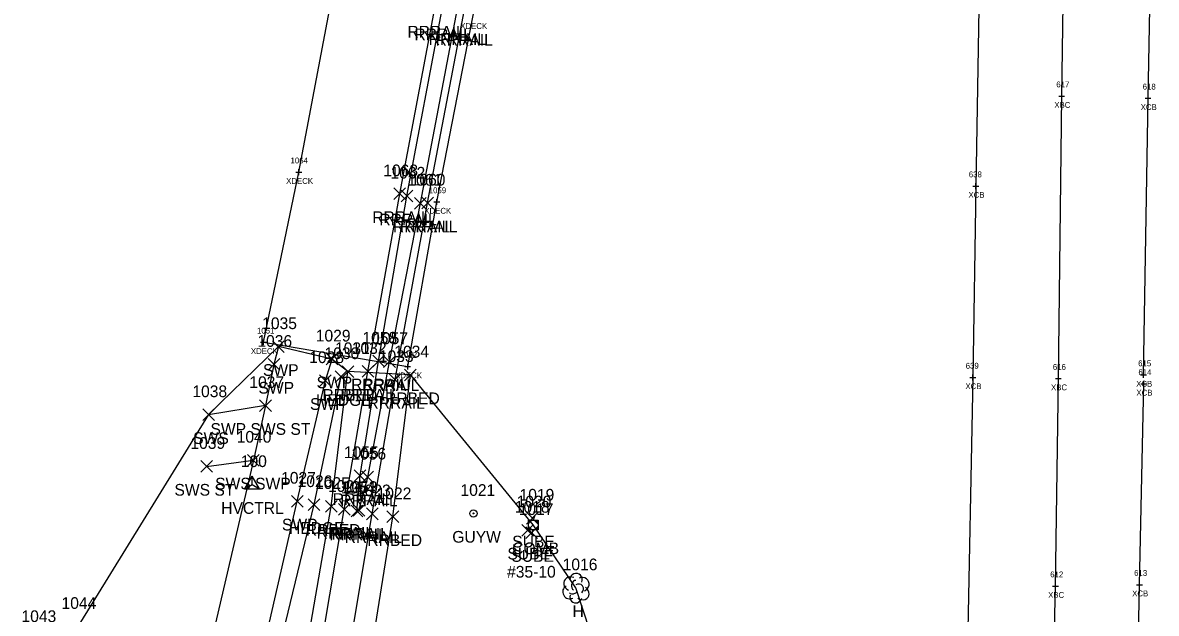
# Model space of a CAD drawing. Extents: x 1715662 to 1717487, y 887396 to 890004.
# Drawn here: x 1716437.2 to 1716631.1, y 888399.3 to 888500.3 of the extents above; entities that cross this region are included whole.
import ezdxf

# ---------------------------------------------------------------- set-up
doc = ezdxf.new("R2010")
doc.units = 0
for name, color, linetype in [('B_A', 7, 'Continuous'), ('B_I', 7, 'Continuous'), ('B_TIC', 7, 'Continuous'), ('BDC', 7, 'Continuous'), ('BELB', 7, 'Continuous'), ('C_A', 7, 'Continuous'), ('C_I', 7, 'Continuous'), ('CPSM', 7, 'Continuous'), ('L_A', 7, 'Continuous'), ('L_I', 7, 'Continuous'), ('L_TIC', 7, 'Continuous'), ('LAHR', 7, 'Continuous'), ('LSOGP', 7, 'Continuous'), ('LTD', 7, 'Continuous'), ('R_A', 7, 'Continuous'), ('R_I', 7, 'Continuous'), ('R_TIC', 7, 'Continuous'), ('RR', 7, 'Continuous'), ('RRB', 7, 'Continuous'), ('RSW', 7, 'Continuous'), ('U_A', 7, 'Continuous'), ('U_C', 7, 'Continuous'), ('U_I', 7, 'Continuous'), ('U_TIC', 7, 'Continuous'), ('UP', 7, 'Continuous'), ('UPGW', 7, 'Continuous')]:
    doc.layers.add(name, color=color, linetype=linetype)

msp = doc.modelspace()

# ---------------------------------------------------------------- linework, layer by layer
at = {"layer": 'B_TIC'}
for p, q in [((1716614.94, 888487.77), (1716615.02, 888487.77)), ((1716629.71, 888487.4), (1716629.79, 888487.4)), ((1716484.45, 888474.77), (1716484.52, 888474.77)), ((1716600.26, 888472.39), (1716600.34, 888472.39)), ((1716508.08, 888469.67), (1716508.15, 888469.67)), ((1716478.41, 888445.68), (1716478.49, 888445.68)), ((1716478.41, 888445.68), (1716478.49, 888445.68)), ((1716503.09, 888441.52), (1716503.16, 888441.52)), ((1716599.73, 888439.67), (1716599.81, 888439.67)), ((1716614.38, 888439.47), (1716614.45, 888439.47)), ((1716628.95, 888440.09), (1716629.02, 888440.09)), ((1716628.99, 888438.57), (1716629.06, 888438.57)), ((1716628.25, 888404.24), (1716628.33, 888404.24)), ((1716613.89, 888403.99), (1716613.97, 888403.99))]:
    msp.add_line(p, q, dxfattribs=at)
for points in [[(1716614.44, 888487.77), (1716615.44, 888487.77)], [(1716614.94, 888487.27), (1716614.94, 888488.27)], [(1716629.71, 888486.9), (1716629.71, 888487.9)], [(1716629.21, 888487.4), (1716630.21, 888487.4)], [(1716483.94, 888474.77), (1716484.94, 888474.77)], [(1716484.44, 888474.27), (1716484.44, 888475.27)], [(1716599.76, 888472.39), (1716600.76, 888472.39)], [(1716600.26, 888471.89), (1716600.26, 888472.89)], [(1716508.07, 888469.17), (1716508.07, 888470.17)], [(1716507.57, 888469.67), (1716508.57, 888469.67)], [(1716477.91, 888445.68), (1716478.91, 888445.68)], [(1716477.91, 888445.68), (1716478.91, 888445.68)], [(1716478.41, 888445.18), (1716478.41, 888446.18)], [(1716478.41, 888445.18), (1716478.41, 888446.18)], [(1716502.58, 888441.52), (1716503.58, 888441.52)], [(1716503.08, 888441.02), (1716503.08, 888442.02)], [(1716599.23, 888439.67), (1716600.23, 888439.67)], [(1716599.73, 888439.17), (1716599.73, 888440.17)], [(1716613.87, 888439.47), (1716614.87, 888439.47)], [(1716614.37, 888438.97), (1716614.37, 888439.97)], [(1716628.44, 888440.09), (1716629.44, 888440.09)], [(1716628.94, 888439.59), (1716628.94, 888440.59)], [(1716628.98, 888438.07), (1716628.98, 888439.07)], [(1716628.48, 888438.57), (1716629.48, 888438.57)], [(1716613.89, 888403.49), (1716613.89, 888404.49)], [(1716627.75, 888404.24), (1716628.75, 888404.24)], [(1716628.25, 888403.74), (1716628.25, 888404.74)], [(1716613.39, 888403.99), (1716614.39, 888403.99)]]:
    msp.add_lwpolyline(points, dxfattribs=at)
at = {"layer": 'BDC'}
for points in [[(1716604.08, 888679.35), (1716603.37, 888635.79), (1716602.62, 888599.38), (1716601.7, 888551.65), (1716601.06, 888519.67), (1716600.26, 888472.39), (1716599.73, 888439.67), (1716598.79, 888390.75), (1716598.29, 888359.77)], [(1716628.94, 888440.09), (1716629.71, 888487.4), (1716630.3, 888518.14)], [(1716628.39, 888359.45), (1716627.88, 888359.84), (1716627.55, 888361.33), (1716627.47, 888363.71), (1716628.25, 888404.24), (1716628.98, 888438.57)]]:
    msp.add_lwpolyline(points, dxfattribs=at)
at = {"layer": 'BELB'}
for points in [[(1716478.41, 888445.68), (1716503.08, 888441.52), (1716508.07, 888469.67), (1716514.21, 888501.26), (1716519.96, 888529.96), (1716525.91, 888559.63), (1716530.47, 888582.92), (1716536.26, 888609.51), (1716540.95, 888632.35), (1716545.99, 888655.48), (1716550.79, 888676.28), (1716540.9, 888678.16), (1716542.76, 888686.4), (1716535.06, 888687.95)], [(1716478.41, 888445.68), (1716484.44, 888474.77), (1716490.12, 888504.65), (1716494.78, 888518.9), (1716497.76, 888535.03), (1716504.02, 888565.38), (1716508.66, 888588.18), (1716513.89, 888613.4), (1716518.93, 888636.07), (1716523.44, 888635.06), (1716528.82, 888659.7), (1716535.06, 888687.95)], [(1716612.85, 888359.68), (1716613.89, 888403.99), (1716614.37, 888439.47), (1716614.94, 888487.77), (1716615.4, 888519.38), (1716616.36, 888571.29), (1716616.55, 888599.24), (1716617.56, 888647.27), (1716618.08, 888679.12)]]:
    msp.add_lwpolyline(points, dxfattribs=at)
at = {"layer": 'CPSM'}
for p, q in [((1716475.23, 888420.63), (1716476.48, 888422.79)), ((1716477.73, 888420.63), (1716476.48, 888422.79)), ((1716476.48, 888421.35), (1716476.48, 888422.79)), ((1716475.23, 888420.63), (1716476.48, 888421.35)), ((1716475.23, 888420.63), (1716477.73, 888420.63)), ((1716476.48, 888421.35), (1716476.48, 888421.35)), ((1716476.48, 888421.35), (1716477.73, 888420.63))]:
    msp.add_line(p, q, dxfattribs=at)
at = {"layer": 'L_TIC'}
for points in [[(1716490.69, 888438.81), (1716492.69, 888440.81)], [(1716492.69, 888438.81), (1716490.69, 888440.81)], [(1716486.07, 888416.93), (1716488.07, 888418.93)], [(1716488.07, 888416.93), (1716486.07, 888418.93)]]:
    msp.add_lwpolyline(points, dxfattribs=at)
at = {"layer": 'LAHR'}
msp.add_lwpolyline([(1716462.99, 888309.04), (1716467.62, 888336.16), (1716473.21, 888363.43), (1716480.22, 888389.65), (1716487.07, 888417.93), (1716491.69, 888439.81)], dxfattribs=at)
at = {"layer": 'LSOGP'}
msp.add_lwpolyline([(1716541.45, 888374.33), (1716531.84, 888403.7), (1716524.56, 888414.45), (1716503.56, 888440.1), (1716492.84, 888440.67), (1716490.12, 888442.81), (1716480.96, 888444.94), (1716469.01, 888433.31), (1716446.64, 888397.1)], dxfattribs=at)
at = {"layer": 'LTD'}
msp.add_line((1716531.84, 888403.7), (1716531.84, 888403.7), dxfattribs=at)
msp.add_line((1716531.84, 888403.7), (1716531.84, 888403.7), dxfattribs=at)
msp.add_arc((1716531.88, 888405.13), 1.05, 335.5272, 180.9563, dxfattribs=at)
for centre, major_axis, ratio, start_param, end_param in [((1716531.04, 888404.37), (1.21, -0.51), 0.895232, 1.570796, 4.712389), ((1716531.63, 888404.16), (-0.208, -0.792), 0.645439, 3.141593, 6.283185), ((1716532.34, 888403.53), (-0.5, 0.667), 0.989748, 3.141593, 6.283185), ((1716532.88, 888404.28), (-1.14, -0.48), 0.949671, 1.570796, 4.712389), ((1716530.75, 888402.99), (0.58, -1.04), 0.959034, 3.141593, 6.283185), ((1716531.84, 888402.2), (0.26, 1.06), 0.942809, 1.570796, 4.712389), ((1716531.38, 888402.95), (-0.625, -0.083), 0.423636, 0, 3.141593), ((1716532.84, 888402.87), (-1.09, 0.79), 0.841452, 1.570796, 4.712389)]:
    msp.add_ellipse(centre, major_axis=major_axis, ratio=ratio, start_param=start_param, end_param=end_param, dxfattribs=at)
at = {"layer": 'R_TIC'}
for points in [[(1716500.72, 888470.07), (1716502.72, 888472.07)], [(1716502.72, 888470.07), (1716500.72, 888472.07)], [(1716501.94, 888469.67), (1716503.94, 888471.67)], [(1716503.94, 888469.67), (1716501.94, 888471.67)], [(1716504.26, 888468.46), (1716506.26, 888470.46)], [(1716506.26, 888468.46), (1716504.26, 888470.46)], [(1716505.48, 888468.5), (1716507.48, 888470.5)], [(1716507.48, 888468.5), (1716505.48, 888470.5)], [(1716479.96, 888443.94), (1716481.96, 888445.94)], [(1716481.96, 888443.94), (1716479.96, 888445.94)], [(1716479.19, 888440.91), (1716481.19, 888442.91)], [(1716481.19, 888440.91), (1716479.19, 888442.91)], [(1716489.13, 888441.82), (1716491.13, 888443.82)], [(1716491.13, 888441.82), (1716489.13, 888443.82)], [(1716497.1, 888441.46), (1716499.1, 888443.46)], [(1716499.1, 888441.46), (1716497.1, 888443.46)], [(1716498.96, 888441.36), (1716500.96, 888443.36)], [(1716500.96, 888441.36), (1716498.96, 888443.36)], [(1716491.84, 888439.67), (1716493.84, 888441.67)], [(1716493.84, 888439.67), (1716491.84, 888441.67)], [(1716495.28, 888439.7), (1716497.28, 888441.7)], [(1716497.28, 888439.7), (1716495.28, 888441.7)], [(1716502.55, 888439.1), (1716504.55, 888441.1)], [(1716504.55, 888439.1), (1716502.55, 888441.1)], [(1716488, 888438.13), (1716490, 888440.13)], [(1716490, 888438.13), (1716488, 888440.13)], [(1716499.91, 888438.31), (1716501.91, 888440.31)], [(1716501.91, 888438.31), (1716499.91, 888440.31)], [(1716477.75, 888433.86), (1716479.75, 888435.86)], [(1716479.75, 888433.86), (1716477.75, 888435.86)], [(1716477.75, 888433.86), (1716479.75, 888435.86)], [(1716479.75, 888433.86), (1716477.75, 888435.86)], [(1716468.01, 888432.3), (1716470.01, 888434.3)], [(1716470.01, 888432.3), (1716468.01, 888434.3)], [(1716467.68, 888423.46), (1716469.68, 888425.46)], [(1716469.68, 888423.46), (1716467.68, 888425.46)], [(1716475.68, 888424.52), (1716477.68, 888426.52)], [(1716477.68, 888424.52), (1716475.68, 888426.52)], [(1716475.68, 888424.52), (1716477.68, 888426.52)], [(1716477.68, 888424.52), (1716475.68, 888426.52)], [(1716493.94, 888421.88), (1716495.94, 888423.88)], [(1716495.94, 888421.88), (1716493.94, 888423.88)], [(1716495.25, 888421.64), (1716497.25, 888423.64)], [(1716497.25, 888421.64), (1716495.25, 888423.64)], [(1716483.19, 888417.51), (1716485.19, 888419.51)], [(1716485.19, 888417.51), (1716483.19, 888419.51)], [(1716488.99, 888416.61), (1716490.99, 888418.61)], [(1716490.99, 888416.61), (1716488.99, 888418.61)], [(1716491.21, 888416.1), (1716493.21, 888418.1)], [(1716493.21, 888416.1), (1716491.21, 888418.1)], [(1716493.39, 888415.83), (1716495.39, 888417.83)], [(1716495.39, 888415.83), (1716493.39, 888417.83)], [(1716493.74, 888415.93), (1716495.74, 888417.93)], [(1716495.74, 888415.93), (1716493.74, 888417.93)], [(1716496, 888415.35), (1716498, 888417.35)], [(1716498, 888415.35), (1716496, 888417.35)], [(1716499.53, 888414.85), (1716501.53, 888416.85)], [(1716501.53, 888414.85), (1716499.53, 888416.85)]]:
    msp.add_lwpolyline(points, dxfattribs=at)
at = {"layer": 'RR'}
for points in [[(1716487.31, 888387.93), (1716492.21, 888417.1), (1716496.28, 888440.7), (1716501.72, 888471.07), (1716507.74, 888502.79), (1716513.46, 888531.59), (1716519.33, 888560.82), (1716524.17, 888584.56), (1716529.26, 888610.21), (1716534.8, 888633.88), (1716539.7, 888657.28), (1716544.48, 888678.15), (1716548.86, 888696.72), (1716554.01, 888719.92)], [(1716492.09, 888386.99), (1716497, 888416.35), (1716500.91, 888439.31), (1716506.48, 888469.5), (1716512.55, 888501.38), (1716518.26, 888530.61), (1716524.3, 888559.71), (1716528.86, 888583.15), (1716534.49, 888608.85), (1716539.41, 888632.6), (1716544.59, 888655.95), (1716549.42, 888676.86), (1716553.66, 888695.32), (1716558.99, 888718.88)], [(1716494.39, 888416.83), (1716494.94, 888422.88), (1716498.1, 888442.46), (1716502.94, 888470.67), (1716508.93, 888502.33), (1716515.06, 888531.51), (1716520.35, 888560.26), (1716525.36, 888584.29), (1716530.64, 888609.99), (1716535.75, 888633.48), (1716541.02, 888656.86), (1716546.22, 888677.74), (1716550.45, 888696.31), (1716552.41, 888702.12)], [(1716494.74, 888416.93), (1716496.25, 888422.64), (1716499.96, 888442.36), (1716505.26, 888469.46), (1716511.38, 888501.53), (1716517.25, 888530.72), (1716522.82, 888559.59), (1716527.83, 888583.61), (1716532.88, 888609.62), (1716538.44, 888633.19), (1716543.26, 888656.01), (1716547.79, 888677.36), (1716551.88, 888695.51), (1716552.71, 888701.89)]]:
    msp.add_lwpolyline(points, dxfattribs=at)
at = {"layer": 'RRB'}
for points in [[(1716470.9, 888275.58), (1716471.7, 888291.33), (1716473.91, 888316.67), (1716477.5, 888334.61), (1716480.65, 888362.31), (1716484.98, 888388.6), (1716489.99, 888417.61), (1716492.84, 888440.67)], [(1716479.97, 888274.17), (1716482.16, 888290.36), (1716485.32, 888314.62), (1716489.5, 888332.4), (1716492.76, 888360.53), (1716495.87, 888386.52), (1716500.53, 888415.85), (1716503.55, 888440.1)]]:
    msp.add_lwpolyline(points, dxfattribs=at)
at = {"layer": 'RSW'}
for points in [[(1716477.61, 888389.85), (1716484.19, 888418.51), (1716489, 888439.13), (1716490.13, 888442.82), (1716480.96, 888444.94), (1716480.19, 888441.91), (1716478.75, 888434.86), (1716476.68, 888425.52), (1716468.03, 888388.37)], [(1716478.75, 888434.86), (1716469.01, 888433.3)], [(1716468.68, 888424.46), (1716476.68, 888425.52)]]:
    msp.add_lwpolyline(points, dxfattribs=at)
at = {"layer": 'U_TIC'}
for points in [[(1716523.41, 888414.61), (1716525.41, 888416.61)], [(1716525.41, 888414.61), (1716523.41, 888416.61)], [(1716522.59, 888412.55), (1716524.59, 888414.55)], [(1716524.59, 888412.55), (1716522.59, 888414.55)], [(1716523.26, 888412.15), (1716525.26, 888414.15)], [(1716525.26, 888412.15), (1716523.26, 888414.15)]]:
    msp.add_lwpolyline(points, dxfattribs=at)
at = {"layer": 'UP'}
for p, q in [((1716524.81, 888416.12), (1716524.56, 888415.28)), ((1716523.73, 888413.62), (1716523.73, 888415.28)), ((1716523.73, 888415.28), (1716525.4, 888415.28)), ((1716524.56, 888414.45), (1716524.56, 888414.45)), ((1716525.4, 888415.28), (1716525.4, 888413.62)), ((1716525.4, 888413.62), (1716523.73, 888413.62)), ((1716524.31, 888412.78), (1716524.56, 888413.62))]:
    msp.add_line(p, q, dxfattribs=at)
msp.add_circle((1716524.56, 888414.45), 0.833, dxfattribs=at)
at = {"layer": 'UPGW'}
for radius in [0.625, 0.0833]:
    msp.add_circle((1716514.31, 888416.42), radius, dxfattribs=at)

# ---------------------------------------------------------------- texts
at = {"layer": 'B_A'}
for s, p in [('XDECK', (1716512.06, 888499.26)), ('XBC', (1716613.68, 888485.77)), ('XCB', (1716628.45, 888485.4)), ('XDECK', (1716482.28, 888472.77)), ('XCB', (1716598.99, 888470.39)), ('XDECK', (1716505.91, 888467.67)), ('XDECK', (1716476.25, 888443.68)), ('XDECK', (1716476.25, 888443.68)), ('XDECK', (1716500.92, 888439.52)), ('XCB', (1716627.68, 888438.09)), ('XCB', (1716598.47, 888437.67)), ('XBC', (1716613.11, 888437.47)), ('XCB', (1716627.72, 888436.57)), ('XBC', (1716612.62, 888401.99)), ('XCB', (1716626.99, 888402.24))]:
    msp.add_text(s, height=1, dxfattribs=at).set_placement(p)
at = {"layer": 'B_I'}
for s, p in [('617', (1716614.02, 888489.27)), ('618', (1716628.79, 888488.9)), ('1064', (1716483.03, 888476.27)), ('638', (1716599.05, 888473.89)), ('1059', (1716506.68, 888471.17)), ('1051', (1716477.3, 888447.18)), ('1051', (1716477.3, 888447.18)), ('1052', (1716501.7, 888443.02)), ('639', (1716598.52, 888441.17)), ('616', (1716613.43, 888440.97)), ('615', (1716628.02, 888441.59)), ('614', (1716628.06, 888440.07)), ('612', (1716612.97, 888405.49)), ('613', (1716627.33, 888405.74))]:
    msp.add_text(s, height=1, dxfattribs=at).set_placement(p)
at = {"layer": 'C_A'}
msp.add_text('HVCTRL', height=2, dxfattribs=at).set_placement((1716471.17, 888416.35))
at = {"layer": 'C_I'}
msp.add_text('100', height=2, dxfattribs=at).set_placement((1716474.52, 888424.35))
at = {"layer": 'L_A'}
for s, p in [('HEDGE', (1716487.4, 888434.81)), ('HEDGE', (1716482.77, 888412.93)), ('H', (1716531.27, 888398.7))]:
    msp.add_text(s, height=2, dxfattribs=at).set_placement(p)
at = {"layer": 'L_I'}
for s, p in [('1030', (1716488.84, 888442.81)), ('1026', (1716484.24, 888420.93)), ('1016', (1716529.58, 888406.7)), ('1044', (1716443.86, 888400.1)), ('1043', (1716437.01, 888397.85))]:
    msp.add_text(s, height=2, dxfattribs=at).set_placement(p)
at = {"layer": 'R_A'}
for s, p in [('RRRAIL', (1716503.03, 888497.79)), ('RRRAIL', (1716504.23, 888497.33)), ('RRRAIL', (1716506.67, 888496.53)), ('RRRAIL', (1716507.84, 888496.38)), ('RRRAIL', (1716497.01, 888466.07)), ('RRRAIL', (1716498.23, 888465.67)), ('RRRAIL', (1716500.55, 888464.46)), ('RRRAIL', (1716501.77, 888464.5)), ('SWP', (1716478.32, 888439.94)), ('SWP', (1716487.49, 888437.82)), ('RRRAIL', (1716493.4, 888437.46)), ('RRRAIL', (1716495.25, 888437.36)), ('SWP', (1716477.55, 888436.91)), ('RRBED', (1716488.49, 888435.67)), ('RRRAIL', (1716491.57, 888435.7)), ('RRBED', (1716499.2, 888435.1)), ('SWP', (1716486.36, 888434.13)), ('RRRAIL', (1716496.2, 888434.31)), ('SWP SWS ST', (1716469.34, 888429.86)), ('SWP SWS ST', (1716469.34, 888429.86)), ('SWS', (1716466.38, 888428.3)), ('SWS SWP', (1716470.14, 888420.52)), ('SWS SWP', (1716470.14, 888420.52)), ('SWS ST', (1716463.18, 888419.46)), ('RRRAIL', (1716490.24, 888417.88)), ('RRRAIL', (1716491.54, 888417.64)), ('SWP', (1716481.56, 888413.51)), ('RRBED', (1716485.64, 888412.61)), ('RRRAIL', (1716487.5, 888412.1)), ('RRRAIL', (1716489.68, 888411.83)), ('RRRAIL', (1716490.04, 888411.93)), ('RRRAIL', (1716492.29, 888411.35)), ('RRBED', (1716496.17, 888410.85))]:
    msp.add_text(s, height=2, dxfattribs=at).set_placement(p)
at = {"layer": 'R_I'}
for s, p in [('1063', (1716498.9, 888474.07)), ('1062', (1716500.12, 888473.67)), ('1061', (1716503.01, 888472.46)), ('1060', (1716503.58, 888472.5)), ('1035', (1716478.18, 888447.94)), ('1036', (1716477.36, 888444.91)), ('1029', (1716487.35, 888445.82)), ('1058', (1716495.33, 888445.46)), ('1057', (1716497.18, 888445.36)), ('1031', (1716490.64, 888443.67)), ('1032', (1716493.51, 888443.7)), ('1034', (1716500.78, 888443.1)), ('1028', (1716486.23, 888442.13)), ('1033', (1716498.14, 888442.31)), ('1037', (1716475.98, 888437.86)), ('1037', (1716475.98, 888437.86)), ('1038', (1716466.24, 888436.3)), ('1039', (1716465.9, 888427.46)), ('1040', (1716473.82, 888428.52)), ('1040', (1716473.82, 888428.52)), ('1055', (1716492.17, 888425.88)), ('1056', (1716493.43, 888425.64)), ('1027', (1716481.42, 888421.51)), ('1025', (1716487.22, 888420.61)), ('1024', (1716489.44, 888420.1)), ('1054', (1716491.62, 888419.83)), ('1053', (1716491.97, 888419.93)), ('1023', (1716494.23, 888419.35)), ('1022', (1716497.75, 888418.85))]:
    msp.add_text(s, height=2, dxfattribs=at).set_placement(p)
at = {"layer": 'U_A'}
for s, p in [('GUYW', (1716510.7, 888411.42)), ('SUBE', (1716520.95, 888410.61)), ('SUBE', (1716520.13, 888408.55)), ('SUBE', (1716520.8, 888408.15)), ('COMB', (1716520.95, 888409.45))]:
    msp.add_text(s, height=2, dxfattribs=at).set_placement(p)
at = {"layer": 'U_C'}
msp.add_text('#35-10', height=2, dxfattribs=at).set_placement((1716520.07, 888405.45))
at = {"layer": 'U_I'}
for s, p in [('1021', (1716512.1, 888419.42)), ('1019', (1716522.2, 888418.61)), ('1018', (1716521.39, 888416.55)), ('1020', (1716521.7, 888417.45)), ('1017', (1716522.06, 888416.15))]:
    msp.add_text(s, height=2, dxfattribs=at).set_placement(p)

doc.saveas('drawing.dxf')
